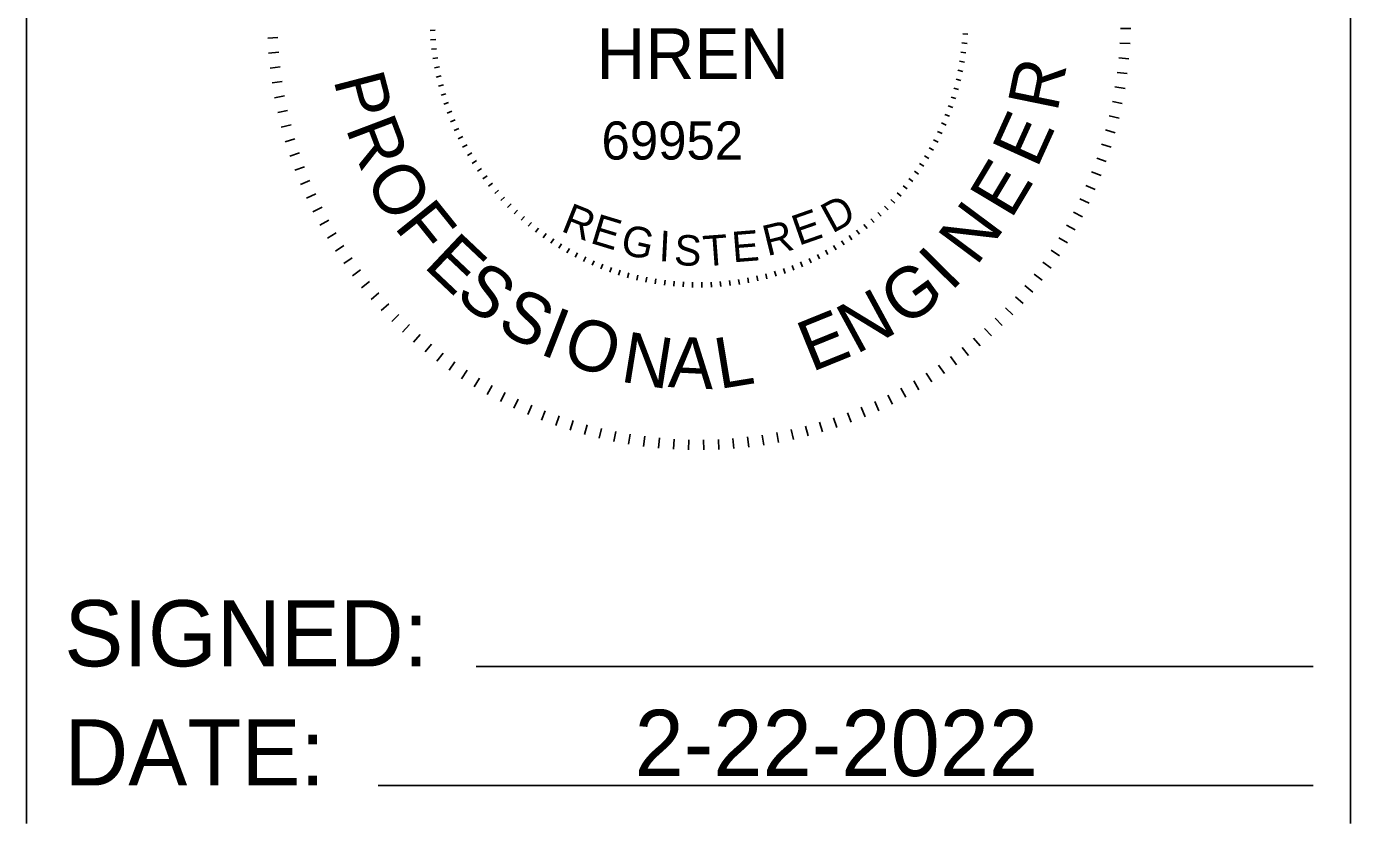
# Model space of a CAD drawing. Extents: x -10 to 89.7, y -4.8 to 22.
# Drawn here: x 8.45 to 11.25, y -4.836 to -3.15 of the extents above; entities that cross this region are included whole.
import ezdxf

# ---------------------------------------------------------------- set-up
doc = ezdxf.new("R2010")
doc.units = 0
doc.layers.add('GM_X_Minor_Lake', color=7, linetype='Continuous')
doc.layers.add('GM_X_Minor_River_Text', color=7, linetype='Continuous')

msp = doc.modelspace()

# ---------------------------------------------------------------- linework, layer by layer
at = {"layer": 'GM_X_Minor_Lake'}
for p, q in [((8.45, -4.8358), (8.45, -1.5858)), ((11.25, -4.8358), (11.25, -1.5858)), ((9.3034, -3.1586), (9.3142, -3.1581)), ((10.7851, -3.1545), (10.7636, -3.1539)), ((8.9601, -3.1744), (8.9816, -3.1734)), ((9.3047, -3.1785), (9.3154, -3.1776)), ((10.4391, -3.1859), (10.4283, -3.1849)), ((10.4406, -3.166), (10.4298, -3.1654)), ((10.7837, -3.1862), (10.7622, -3.185)), ((8.9621, -3.2062), (8.9834, -3.2045)), ((9.3067, -3.1982), (9.3173, -3.197)), ((9.3093, -3.218), (9.3199, -3.2164)), ((10.4368, -3.2056), (10.4262, -3.2042)), ((10.7813, -3.2181), (10.7598, -3.216)), ((8.9652, -3.2379), (8.9866, -3.2355)), ((9.3126, -3.2375), (9.3232, -3.2356)), ((10.4303, -3.2449), (10.4198, -3.2427)), ((10.4339, -3.2252), (10.4233, -3.2235)), ((10.7777, -3.2497), (10.7564, -3.247)), ((8.9694, -3.2695), (8.9907, -3.2662)), ((9.3166, -3.257), (9.3271, -3.2546)), ((9.3213, -3.2764), (9.3317, -3.2736)), ((10.4261, -3.2642), (10.4157, -3.2617)), ((8.9748, -3.301), (8.9958, -3.297)), ((9.3267, -3.2955), (9.3369, -3.2924)), ((10.4156, -3.3025), (10.4053, -3.2994)), ((10.4212, -3.2835), (10.4108, -3.2806)), ((10.7731, -3.2812), (10.7519, -3.2777)), ((8.9812, -3.3321), (9.0022, -3.3275)), ((9.3327, -3.3144), (9.3428, -3.311)), ((9.3393, -3.3331), (9.3494, -3.3294)), ((10.4093, -3.3214), (10.3992, -3.3179)), ((10.7673, -3.3126), (10.7463, -3.3084)), ((8.9887, -3.3631), (9.0094, -3.3577)), ((9.3467, -3.3516), (9.3566, -3.3475)), ((10.3948, -3.3584), (10.3849, -3.3541)), ((10.4023, -3.34), (10.3923, -3.3361)), ((10.7606, -3.3437), (10.7396, -3.3387)), ((8.9973, -3.3939), (9.0178, -3.3876)), ((9.3547, -3.3697), (9.3644, -3.3654)), ((9.3632, -3.3877), (9.3728, -3.3829)), ((10.3866, -3.3765), (10.3769, -3.3719)), ((10.7526, -3.3746), (10.7319, -3.3689)), ((9.3724, -3.4054), (9.3818, -3.4001)), ((10.3683, -3.4119), (10.3589, -3.4065)), ((10.3778, -3.3944), (10.3682, -3.3894)), ((10.7436, -3.4052), (10.7231, -3.3987)), ((9.0069, -3.4242), (9.0273, -3.4174)), ((9.3823, -3.4226), (9.3916, -3.4171)), ((9.3927, -3.4395), (9.4017, -3.4337)), ((10.3477, -3.4457), (10.3387, -3.4399)), ((10.3583, -3.429), (10.3491, -3.4234)), ((10.7336, -3.4355), (10.7133, -3.4284)), ((9.0177, -3.4542), (9.0377, -3.4466)), ((9.4037, -3.4561), (9.4126, -3.45)), ((9.4153, -3.4722), (9.4239, -3.4659)), ((10.3247, -3.4781), (10.3161, -3.4716)), ((10.3364, -3.4621), (10.3277, -3.4559)), ((10.7224, -3.4654), (10.7024, -3.4575)), ((9.0293, -3.4839), (9.0492, -3.4756)), ((9.4274, -3.488), (9.4358, -3.4812)), ((9.4401, -3.5032), (9.4482, -3.4962)), ((10.3123, -3.4937), (10.3039, -3.4869)), ((10.7103, -3.4947), (10.6906, -3.4862)), ((9.0422, -3.513), (9.0617, -3.5041)), ((9.4533, -3.5181), (9.4612, -3.5109)), ((9.4669, -3.5325), (9.4747, -3.525)), ((10.2861, -3.5235), (10.2782, -3.5161)), ((10.2994, -3.5089), (10.2913, -3.5017)), ((10.6972, -3.5239), (10.6778, -3.5146)), ((9.0559, -3.5417), (9.0752, -3.5321)), ((9.4812, -3.5464), (9.4886, -3.5386)), ((9.4958, -3.5597), (9.5029, -3.5517)), ((10.2577, -3.5515), (10.2504, -3.5436)), ((10.2722, -3.5377), (10.2646, -3.5301)), ((10.6831, -3.5524), (10.6639, -3.5425)), ((9.0707, -3.57), (9.0896, -3.5597)), ((9.5111, -3.5726), (9.5178, -3.5644)), ((9.5266, -3.585), (9.5331, -3.5765)), ((10.2118, -3.5895), (10.2054, -3.5809)), ((10.2276, -3.5774), (10.2209, -3.569)), ((10.2429, -3.5646), (10.2359, -3.5565)), ((10.6679, -3.5804), (10.6492, -3.5699)), ((9.0864, -3.5977), (9.1049, -3.5867)), ((9.5426, -3.5967), (9.5488, -3.588)), ((9.5589, -3.608), (9.5649, -3.599)), ((9.5758, -3.6186), (9.5813, -3.6095)), ((10.1792, -3.612), (10.1733, -3.603)), ((10.1957, -3.601), (10.1896, -3.5922)), ((10.6518, -3.6079), (10.6334, -3.5967)), ((9.1032, -3.6249), (9.1213, -3.6132)), ((9.1208, -3.6514), (9.1386, -3.6392)), ((9.5929, -3.6287), (9.5982, -3.6194)), ((9.6104, -3.6381), (9.6153, -3.6286)), ((9.6282, -3.647), (9.6328, -3.6372)), ((10.1273, -3.6415), (10.1226, -3.6319)), ((10.1449, -3.6322), (10.1398, -3.6229)), ((10.1622, -3.6225), (10.1567, -3.6132)), ((10.6347, -3.6349), (10.6168, -3.623)), ((9.1394, -3.6772), (9.1567, -3.6645)), ((9.6463, -3.6551), (9.6506, -3.6454)), ((9.6647, -3.6627), (9.6686, -3.6527)), ((9.6833, -3.6696), (9.6869, -3.6595)), ((9.7022, -3.6759), (9.7054, -3.6656)), ((10.0351, -3.6781), (10.0321, -3.6677)), ((10.0541, -3.6721), (10.0506, -3.6619)), ((10.0727, -3.6654), (10.0689, -3.6554)), ((10.0912, -3.6581), (10.0871, -3.6481)), ((10.1094, -3.6501), (10.1049, -3.6404)), ((10.6167, -3.6611), (10.5992, -3.6487)), ((9.1588, -3.7025), (9.1757, -3.6891)), ((9.7212, -3.6815), (9.7241, -3.6711)), ((9.7404, -3.6865), (9.7429, -3.676)), ((9.7599, -3.6907), (9.7621, -3.6801)), ((9.7794, -3.6942), (9.7812, -3.6837)), ((9.7991, -3.6972), (9.8004, -3.6865)), ((9.8188, -3.6994), (9.8198, -3.6887)), ((9.8387, -3.7009), (9.8393, -3.6901)), ((9.8586, -3.7017), (9.8588, -3.691)), ((9.8784, -3.7019), (9.8783, -3.6911)), ((9.8983, -3.7012), (9.8978, -3.6906)), ((9.9181, -3.7), (9.9172, -3.6894)), ((9.9379, -3.6981), (9.9367, -3.6874)), ((9.9576, -3.6955), (9.9559, -3.6849)), ((9.9772, -3.6921), (9.9752, -3.6816)), ((9.9967, -3.6881), (9.9943, -3.6776)), ((10.0159, -3.6835), (10.0132, -3.673)), ((10.5978, -3.6867), (10.5807, -3.6737)), ((9.1792, -3.7271), (9.1954, -3.7131)), ((10.5574, -3.7361), (10.5413, -3.7219)), ((10.5781, -3.7117), (10.5614, -3.6981)), ((9.2003, -3.7509), (9.2162, -3.7364)), ((10.5359, -3.7596), (10.5203, -3.7449)), ((9.2223, -3.774), (9.2377, -3.7589)), ((10.5136, -3.7824), (10.4986, -3.7671)), ((9.2451, -3.7962), (9.2598, -3.7806)), ((9.2687, -3.8177), (9.2828, -3.8016)), ((10.4906, -3.8044), (10.4759, -3.7886)), ((9.2929, -3.8384), (9.3066, -3.8217)), ((10.4422, -3.8459), (10.4288, -3.8291)), ((10.4667, -3.8256), (10.4527, -3.8092)), ((9.3179, -3.8581), (9.3309, -3.8411)), ((9.3436, -3.8771), (9.3561, -3.8596)), ((10.4169, -3.8654), (10.4041, -3.8481)), ((9.3699, -3.8951), (9.3817, -3.8771)), ((10.3644, -3.9015), (10.3529, -3.8835)), ((10.3911, -3.8839), (10.3788, -3.8662)), ((9.3968, -3.9121), (9.4079, -3.8937)), ((9.4243, -3.9282), (9.4348, -3.9095)), ((10.3097, -3.934), (10.2993, -3.9151)), ((10.3373, -3.9182), (10.3264, -3.8997)), ((9.4523, -3.9434), (9.4622, -3.9244)), ((9.4809, -3.9576), (9.4901, -3.9381)), ((10.2527, -3.9626), (10.2437, -3.9431)), ((10.2814, -3.9487), (10.2718, -3.9296)), ((9.5099, -3.9707), (9.5184, -3.951)), ((9.5394, -3.9829), (9.5472, -3.9629)), ((9.5693, -3.994), (9.5764, -3.9736)), ((10.1938, -3.9871), (10.1863, -3.967)), ((10.2234, -3.9754), (10.2152, -3.9555)), ((9.5996, -4.004), (9.6059, -3.9835)), ((9.6301, -4.013), (9.6358, -3.9922)), ((9.6609, -4.0209), (9.6659, -4)), ((10.0718, -4.0236), (10.0671, -4.0026)), ((10.1028, -4.016), (10.0973, -3.9952)), ((10.1334, -4.0075), (10.1273, -3.9869)), ((10.1638, -3.9979), (10.1569, -3.9775)), ((9.6921, -4.0277), (9.6963, -4.0066)), ((9.7234, -4.0335), (9.7269, -4.0122)), ((9.7549, -4.0381), (9.7578, -4.0167)), ((9.7867, -4.0416), (9.7887, -4.0202)), ((9.8184, -4.0441), (9.8197, -4.0226)), ((9.8503, -4.0454), (9.8508, -4.0239)), ((9.8822, -4.0456), (9.8819, -4.0241)), ((9.9141, -4.0446), (9.9131, -4.0232)), ((9.9458, -4.0426), (9.9441, -4.0212)), ((9.9776, -4.0395), (9.9751, -4.0182)), ((10.0092, -4.0354), (10.0059, -4.0141)), ((10.0406, -4.03), (10.0366, -4.0089))]:
    msp.add_line(p, q, dxfattribs=at)
at = {"layer": 'GM_X_Minor_River_Text'}
for p, q in [((9.4011, -4.5034), (11.1713, -4.5034)), ((9.1934, -4.7553), (11.1713, -4.7553))]:
    msp.add_line(p, q, dxfattribs=at)

# ---------------------------------------------------------------- texts
at = {"layer": 'GM_X_Minor_Lake'}
for s, height, p in [('HREN', 0.10742, (9.655, -3.2611)), ('69952', 0.08057, (9.666, -3.4314))]:
    msp.add_text(s, height=height, dxfattribs=at).set_placement(p)
for s, height, rotation, p in [('P', 0.1074, 284.5881, (9.0987, -3.2622)), ('R', 0.1074, 78.4293, (10.6297, -3.3331)), ('E', 0.1074, 65.6605, (10.5869, -3.4521)), ('R', 0.1074, 290.7551, (9.1241, -3.3651)), ('O', 0.1074, 300.8517, (9.1633, -3.4745)), ('E', 0.1074, 59.1145, (10.5323, -3.5595)), ('F', 0.1074, 308.7588, (9.2257, -3.5741)), ('R', 0.0645, 338.1521, (9.5782, -3.582)), ('D', 0.0645, 28.7189, (10.1541, -3.5885)), ('N', 0.1074, 53.3219, (10.4584, -3.6586)), ('E', 0.0645, 343.0656, (9.6399, -3.6071)), ('E', 0.0645, 19.2812, (10.0832, -3.6141)), ('G', 0.0645, 347.1787, (9.7034, -3.6298)), ('I', 0.0645, 357.1579, (9.7863, -3.646)), ('E', 0.0645, 4.5855, (9.9441, -3.649)), ('R', 0.0645, 13.7281, (10.0163, -3.6359)), ('E', 0.1074, 316.6179, (9.2877, -3.6577)), ('S', 0.0645, 356.6595, (9.8183, -3.654)), ('T', 0.0645, 4.2417, (9.8829, -3.6575)), ('I', 0.1074, 45.3435, (10.4048, -3.7121)), ('S', 0.1074, 322.2586, (9.3533, -3.7235)), ('G', 0.1074, 36.0675, (10.3067, -3.7882)), ('S', 0.1074, 331.7014, (9.4413, -3.7909)), ('N', 0.1074, 28.5465, (10.2044, -3.8444)), ('I', 0.1074, 338.6655, (9.532, -3.8414)), ('E', 0.1074, 22.0631, (10.1104, -3.8815)), ('O', 0.1074, 341.7879, (9.5784, -3.8594)), ('N', 0.1074, 350.8395, (9.7039, -3.9007)), ('A', 0.1074, 357.1724, (9.8057, -3.9125)), ('L', 0.1074, 9.318, (9.9149, -3.917))]:
    msp.add_text(s, height=height, rotation=rotation, dxfattribs=at).set_placement(p)
at = {"layer": 'GM_X_Minor_River_Text'}
for s, p in [('SIGNED:', (8.53, -4.5034)), ('DATE:', (8.53, -4.7553)), ('2-22-2022', (9.7361, -4.7353))]:
    msp.add_text(s, height=0.14, dxfattribs=at).set_placement(p)

doc.saveas('drawing.dxf')
